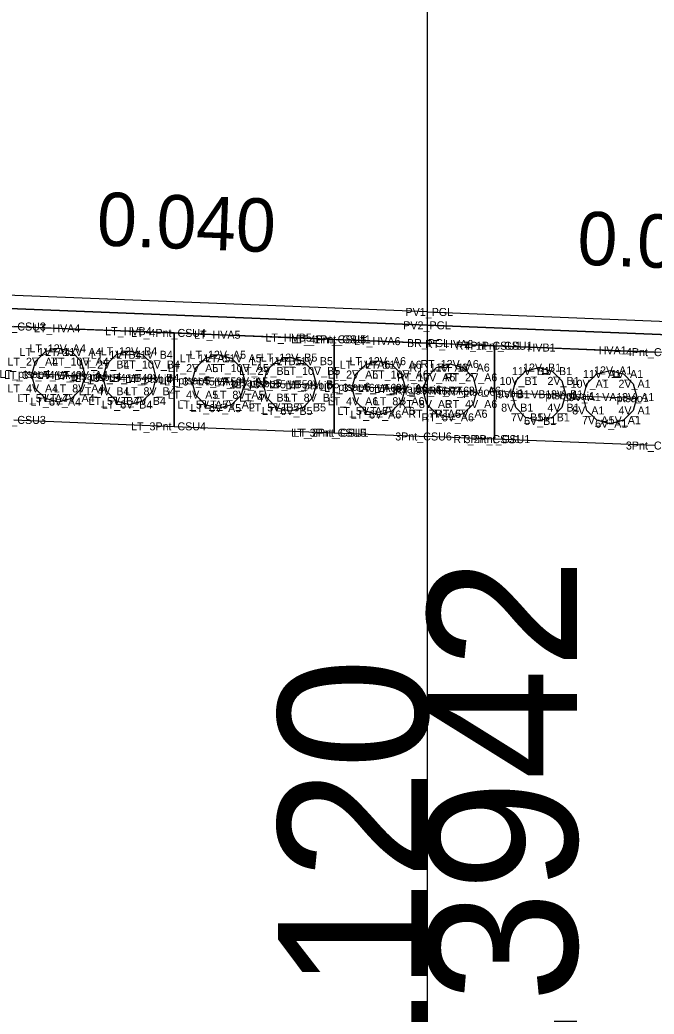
# Model space of a CAD drawing. Extents: x -26 to 1163, y -10 to 9537.
# Drawn here: x 72.36 to 84.24, y 6008.93 to 6027.56 of the extents above; entities that cross this region are included whole.
import ezdxf

# ---------------------------------------------------------------- set-up
doc = ezdxf.new("R2010")
doc.units = 0
for name, color, linetype in [('Exist Cross Section Cell', 7, 'Continuous'), ('Prop CMT Concrete Structures', 7, 'Continuous'), ('Prop CMT Corridor Surface Symbology Blue', 7, 'Continuous'), ('Prop CMT Pvmt Course 1', 7, 'Continuous'), ('Prop CMT Pvmt Course 2', 7, 'Continuous'), ('Prop XS SE Text', 7, 'Continuous'), ('Scratch_Level_0', 7, 'Continuous')]:
    doc.layers.add(name, color=color, linetype=linetype)

msp = doc.modelspace()

# ---------------------------------------------------------------- linework, layer by layer
at = {"layer": 'Exist Cross Section Cell'}
msp.add_line((80, 6000), (80, 6061.321), dxfattribs=at)
at = {"layer": 'Prop CMT Concrete Structures'}
for points in [[(75.25, 6021.697), (74.417, 6021.73), (73.083, 6021.783), (72.25, 6021.817)], [(78.25, 6021.577), (77.417, 6021.61), (76.083, 6021.663), (75.25, 6021.697)], [(75.25, 6021.697), (75.25, 6019.947)], [(75.25, 6019.947), (75.25, 6021.697)], [(80, 6021.507), (79.083, 6021.543), (78.25, 6021.577)], [(78.25, 6021.577), (78.25, 6019.827)], [(78.25, 6019.827), (78.25, 6021.577)], [(73.083, 6021.408), (72.833, 6021.341), (72.65, 6021.158), (72.583, 6020.908)], [(73.583, 6020.908), (73.516, 6021.158), (73.333, 6021.341), (73.083, 6021.408)], [(74.417, 6021.355), (74.167, 6021.288), (73.984, 6021.105), (73.917, 6020.855)], [(74.917, 6020.855), (74.85, 6021.105), (74.667, 6021.288), (74.417, 6021.355)], [(80, 6019.757), (80, 6021.507)], [(80, 6021.507), (80.417, 6021.49), (81.25, 6021.457)], [(80, 6019.757), (80, 6021.507)], [(81.25, 6021.457), (81.25, 6019.707)], [(81.25, 6021.457), (82.083, 6021.423), (83.417, 6021.37), (84.25, 6021.337)], [(81.25, 6019.707), (81.25, 6021.457)], [(76.083, 6021.288), (75.833, 6021.221), (75.65, 6021.038), (75.583, 6020.788)], [(76.583, 6020.788), (76.516, 6021.038), (76.333, 6021.221), (76.083, 6021.288)], [(77.417, 6021.235), (77.167, 6021.168), (76.984, 6020.985), (76.917, 6020.735)], [(77.917, 6020.735), (77.85, 6020.985), (77.667, 6021.168), (77.417, 6021.235)], [(79.083, 6021.168), (78.833, 6021.101), (78.65, 6020.918), (78.583, 6020.668)], [(79.583, 6020.668), (79.516, 6020.918), (79.333, 6021.101), (79.083, 6021.168)], [(79.917, 6020.615), (79.984, 6020.865), (80.167, 6021.048), (80.417, 6021.115)], [(80.417, 6021.115), (80.667, 6021.048), (80.85, 6020.865), (80.917, 6020.615)], [(81.583, 6020.548), (81.65, 6020.798), (81.833, 6020.981), (82.083, 6021.048)], [(82.083, 6021.048), (82.333, 6020.981), (82.516, 6020.798), (82.583, 6020.548)], [(82.917, 6020.495), (82.984, 6020.745), (83.167, 6020.928), (83.417, 6020.995)], [(83.417, 6020.995), (83.667, 6020.928), (83.85, 6020.745), (83.917, 6020.495)], [(72.583, 6020.908), (72.65, 6020.658), (72.833, 6020.475), (73.083, 6020.408), (73.333, 6020.475), (73.516, 6020.658), (73.583, 6020.908)], [(73.917, 6020.855), (73.984, 6020.605), (74.167, 6020.422), (74.417, 6020.355), (74.667, 6020.422), (74.85, 6020.605), (74.917, 6020.855)], [(75.583, 6020.788), (75.65, 6020.538), (75.833, 6020.355), (76.083, 6020.288), (76.333, 6020.355), (76.516, 6020.538), (76.583, 6020.788)], [(76.917, 6020.735), (76.984, 6020.485), (77.167, 6020.302), (77.417, 6020.235), (77.667, 6020.302), (77.85, 6020.485), (77.917, 6020.735)], [(78.583, 6020.668), (78.65, 6020.418), (78.833, 6020.235), (79.083, 6020.168), (79.333, 6020.235), (79.516, 6020.418), (79.583, 6020.668)], [(80.917, 6020.615), (80.85, 6020.365), (80.667, 6020.182), (80.417, 6020.115), (80.167, 6020.182), (79.984, 6020.365), (79.917, 6020.615)], [(82.583, 6020.548), (82.516, 6020.298), (82.333, 6020.115), (82.083, 6020.048), (81.833, 6020.115), (81.65, 6020.298), (81.583, 6020.548)], [(83.917, 6020.495), (83.85, 6020.245), (83.667, 6020.062), (83.417, 6019.995), (83.167, 6020.062), (82.984, 6020.245), (82.917, 6020.495)], [(72.25, 6020.067), (75.25, 6019.947)], [(75.25, 6019.947), (78.25, 6019.827)], [(78.25, 6019.827), (80, 6019.757)], [(81.25, 6019.707), (80, 6019.757)], [(84.25, 6019.587), (81.25, 6019.707)]]:
    msp.add_lwpolyline(points, dxfattribs=at)
at = {"layer": 'Prop CMT Corridor Surface Symbology Blue'}
for points in [[(73.573, 6020.889), (73.083, 6020.908), (72.593, 6020.928)], [(74.907, 6020.835), (74.417, 6020.855), (73.927, 6020.875)], [(76.573, 6020.769), (76.083, 6020.788), (75.593, 6020.808)], [(77.907, 6020.715), (77.417, 6020.735), (76.927, 6020.755)], [(79.573, 6020.649), (79.083, 6020.668), (78.593, 6020.688)], [(79.927, 6020.635), (80.417, 6020.615), (80.907, 6020.595)], [(81.593, 6020.568), (82.083, 6020.548), (82.573, 6020.529)], [(82.927, 6020.515), (83.417, 6020.495), (83.907, 6020.475)]]:
    msp.add_lwpolyline(points, dxfattribs=at)
at = {"layer": 'Prop CMT Pvmt Course 1'}
for points in [[(80, 6022.09), (71, 6022.45), (61.5, 6022.83)], [(61.5, 6022.58), (80, 6021.84)], [(80, 6021.84), (80, 6022.09)], [(80, 6022.09), (89, 6021.73), (98.376, 6021.355)], [(80, 6021.84), (80, 6022.09)], [(98.376, 6021.355), (98.376, 6021.105), (80, 6021.84)]]:
    msp.add_lwpolyline(points, dxfattribs=at)
at = {"layer": 'Prop CMT Pvmt Course 2'}
for points in [[(80, 6021.84), (61.5, 6022.58)], [(61.5, 6022.58), (61.5, 6022.247), (80, 6021.507)], [(80, 6021.507), (80, 6021.84)], [(80, 6021.84), (98.376, 6021.105)], [(80, 6021.507), (80, 6021.84)], [(98.376, 6021.105), (98.375, 6020.772), (80, 6021.507)]]:
    msp.add_lwpolyline(points, dxfattribs=at)

# ---------------------------------------------------------------- texts
at = {"layer": 'Exist Cross Section Cell'}
for s, p in [('E 2058824.3942', (82.8, 5990)), ('N 688767.1120', (80, 5990))]:
    msp.add_text(s, height=2.8, rotation=90, dxfattribs=at).set_placement(p)
at = {"layer": 'Prop XS SE Text'}
for p in [(73.791, 6023.339), (82.791, 6022.979)]:
    msp.add_text('0.040', height=1, rotation=357.7094, dxfattribs=at).set_placement(p)
at = {"layer": 'Scratch_Level_0'}
for s, p in [('PV1_PGL', (79.585, 6022.015)), ('LT_4Pnt_CSU3', (71.444, 6021.742)), ('PV2_PGL', (79.543, 6021.765)), ('LT_HVA4', (72.625, 6021.708)), ('LT_HVB4', (73.961, 6021.655)), ('LT_4Pnt_CSU4', (74.444, 6021.622)), ('LT_HVA5', (75.625, 6021.588)), ('LT_HVB5', (76.961, 6021.535)), ('LT_4Pnt_CSU5', (77.444, 6021.502)), ('LT_1Pnt_CSU1', (77.53, 6021.502)), ('LT_HVA6', (78.622, 6021.468)), ('BR_PGL', (79.613, 6021.432)), ('RT_HVA6', (79.951, 6021.415)), ('RT_1Pnt_CSU1', (80.526, 6021.382)), ('4Pnt_CSU1', (80.689, 6021.382)), ('LT_1V_A4', (72.356, 6021.266)), ('LT_12V_A4', (72.539, 6021.333)), ('LT_11V_A4', (72.831, 6021.266)), ('LT_1V_B4', (73.692, 6021.213)), ('LT_12V_B4', (73.875, 6021.28)), ('LT_11V_B4', (74.167, 6021.213)), ('LT_12V_A5', (75.539, 6021.213)), ('HVB1', (81.872, 6021.348)), ('HVA1', (83.203, 6021.295)), ('4Pnt_CSU', (83.714, 6021.262)), ('LT_2V_A4', (72.131, 6021.083)), ('LT_10V_A4', (72.966, 6021.083)), ('LT_2V_B4', (73.466, 6021.03)), ('LT_10V_B4', (74.302, 6021.03)), ('LT_1V_A5', (75.356, 6021.146)), ('LT_11V_A5', (75.831, 6021.146)), ('LT_1V_B5', (76.692, 6021.093)), ('LT_12V_B5', (76.875, 6021.16)), ('LT_11V_B5', (77.167, 6021.093)), ('LT_1V_A6', (78.353, 6021.026)), ('LT_12V_A6', (78.535, 6021.093)), ('LT_11V_A6', (78.828, 6021.026)), ('RT_12V_A6', (79.865, 6021.04)), ('LT_ptsao4', (71.982, 6020.853)), ('LT_3V_A4', (72.064, 6020.833)), ('LT_VA4', (72.692, 6020.833)), ('LT_ptsai4', (73.002, 6020.814)), ('LT_9V_A4', (73.064, 6020.833)), ('LT_ptsbo4', (73.316, 6020.8)), ('LT_2V_A5', (75.131, 6020.963)), ('LT_10V_A5', (75.966, 6020.963)), ('LT_2V_B5', (76.466, 6020.91)), ('LT_10V_B5', (77.302, 6020.91)), ('LT_2V_A6', (78.127, 6020.843)), ('LT_10V_A6', (78.962, 6020.843)), ('RT_11V_A6', (79.658, 6020.973)), ('RT_1V_A6', (80.182, 6020.973)), ('11V_B1', (81.578, 6020.906)), ('12V_B1', (81.786, 6020.973)), ('1V_B1', (82.103, 6020.906)), ('11V_A1', (82.909, 6020.853)), ('12V_A1', (83.117, 6020.92)), ('1V_A1', (83.434, 6020.853)), ('LT_3V_B4', (73.399, 6020.78)), ('LT_VB4', (74.028, 6020.78)), ('LT_ptsbi4', (74.336, 6020.76)), ('LT_9V_B4', (74.399, 6020.78)), ('LT_ptsao5', (74.982, 6020.733)), ('LT_3V_A5', (75.064, 6020.713)), ('LT_VA5', (75.692, 6020.713)), ('LT_ptsai5', (76.002, 6020.694)), ('LT_9V_A5', (76.064, 6020.713)), ('LT_ptsbo5', (76.316, 6020.68)), ('LT_3V_B5', (76.399, 6020.66)), ('LT_VB5', (77.028, 6020.66)), ('LT_ptsbi5', (77.336, 6020.64)), ('LT_9V_B5', (77.399, 6020.66)), ('RT_10V_A6', (79.426, 6020.79)), ('RT_2V_A6', (80.323, 6020.79)), ('10V_B1', (81.347, 6020.723)), ('2V_B1', (82.244, 6020.723)), ('10V_A1', (82.678, 6020.67)), ('2V_A1', (83.574, 6020.67)), ('LT_4V_A4', (72.131, 6020.583)), ('LT_8V_A4', (72.997, 6020.583)), ('LT_4V_B4', (73.466, 6020.53)), ('LT_8V_B4', (74.332, 6020.53)), ('LT_4V_A5', (75.131, 6020.463)), ('LT_8V_A5', (75.997, 6020.463)), ('LT_ptsao6', (77.978, 6020.613)), ('LT_3V_A6', (78.06, 6020.593)), ('LT_VA6', (78.689, 6020.593)), ('LT_ptsai6', (78.998, 6020.574)), ('LT_9V_A6', (79.06, 6020.593)), ('RT_ptsai6', (79.348, 6020.56)), ('RT_9V_A6', (79.39, 6020.54)), ('RT_VA6', (80.019, 6020.54)), ('RT_ptsao6', (80.288, 6020.52)), ('RT_3V_A6', (80.39, 6020.54)), ('ptsbi1', (81.267, 6020.493)), ('9V_B1', (81.31, 6020.473)), ('VB1', (81.939, 6020.473)), ('ptsbo1', (82.207, 6020.454)), ('3V_B1', (82.31, 6020.473)), ('ptsai1', (82.6, 6020.44)), ('LT_5V_A4', (72.314, 6020.4)), ('LT_6V_A4', (72.56, 6020.333)), ('LT_7V_A4', (72.814, 6020.4)), ('LT_5V_B4', (73.649, 6020.347)), ('LT_6V_B4', (73.896, 6020.28)), ('LT_7V_B4', (74.149, 6020.347)), ('LT_5V_A5', (75.314, 6020.28)), ('LT_7V_A5', (75.814, 6020.28)), ('LT_4V_B5', (76.466, 6020.41)), ('LT_8V_B5', (77.332, 6020.41)), ('LT_4V_A6', (78.127, 6020.343)), ('LT_8V_A6', (78.993, 6020.343)), ('RT_8V_A6', (79.457, 6020.29)), ('RT_4V_A6', (80.323, 6020.29)), ('9V_A1', (82.641, 6020.42)), ('VA1', (83.27, 6020.42)), ('ptsao1', (83.539, 6020.4)), ('3V_A1', (83.641, 6020.42)), ('LT_6V_A5', (75.56, 6020.213)), ('LT_5V_B5', (76.649, 6020.227)), ('LT_6V_B5', (76.896, 6020.16)), ('LT_7V_B5', (77.149, 6020.227)), ('LT_5V_A6', (78.31, 6020.16)), ('LT_6V_A6', (78.557, 6020.093)), ('LT_7V_A6', (78.81, 6020.16)), ('RT_7V_A6', (79.64, 6020.107)), ('RT_5V_A6', (80.14, 6020.107)), ('8V_B1', (81.377, 6020.223)), ('4V_B1', (82.244, 6020.223)), ('8V_A1', (82.708, 6020.17)), ('4V_A1', (83.574, 6020.17)), ('LT_3Pnt_CSU3', (71.444, 6019.992)), ('RT_6V_A6', (79.886, 6020.04)), ('7V_B1', (81.56, 6020.04)), ('6V_B1', (81.807, 6019.973)), ('5V_B1', (82.06, 6020.04)), ('7V_A1', (82.891, 6019.987)), ('6V_A1', (83.138, 6019.92)), ('5V_A1', (83.391, 6019.987)), ('LT_3Pnt_CSU4', (74.444, 6019.872)), ('LT_3Pnt_CSU5', (77.444, 6019.752)), ('LT_2Pnt_CSU1', (77.487, 6019.752)), ('3Pnt_CSU6', (79.393, 6019.682)), ('RT_2Pnt_CSU1', (80.483, 6019.632)), ('3Pnt_CSU1', (80.689, 6019.632)), ('3Pnt_CSU', (83.714, 6019.512))]:
    msp.add_text(s, height=0.15, dxfattribs=at).set_placement(p)

doc.saveas('drawing.dxf')
